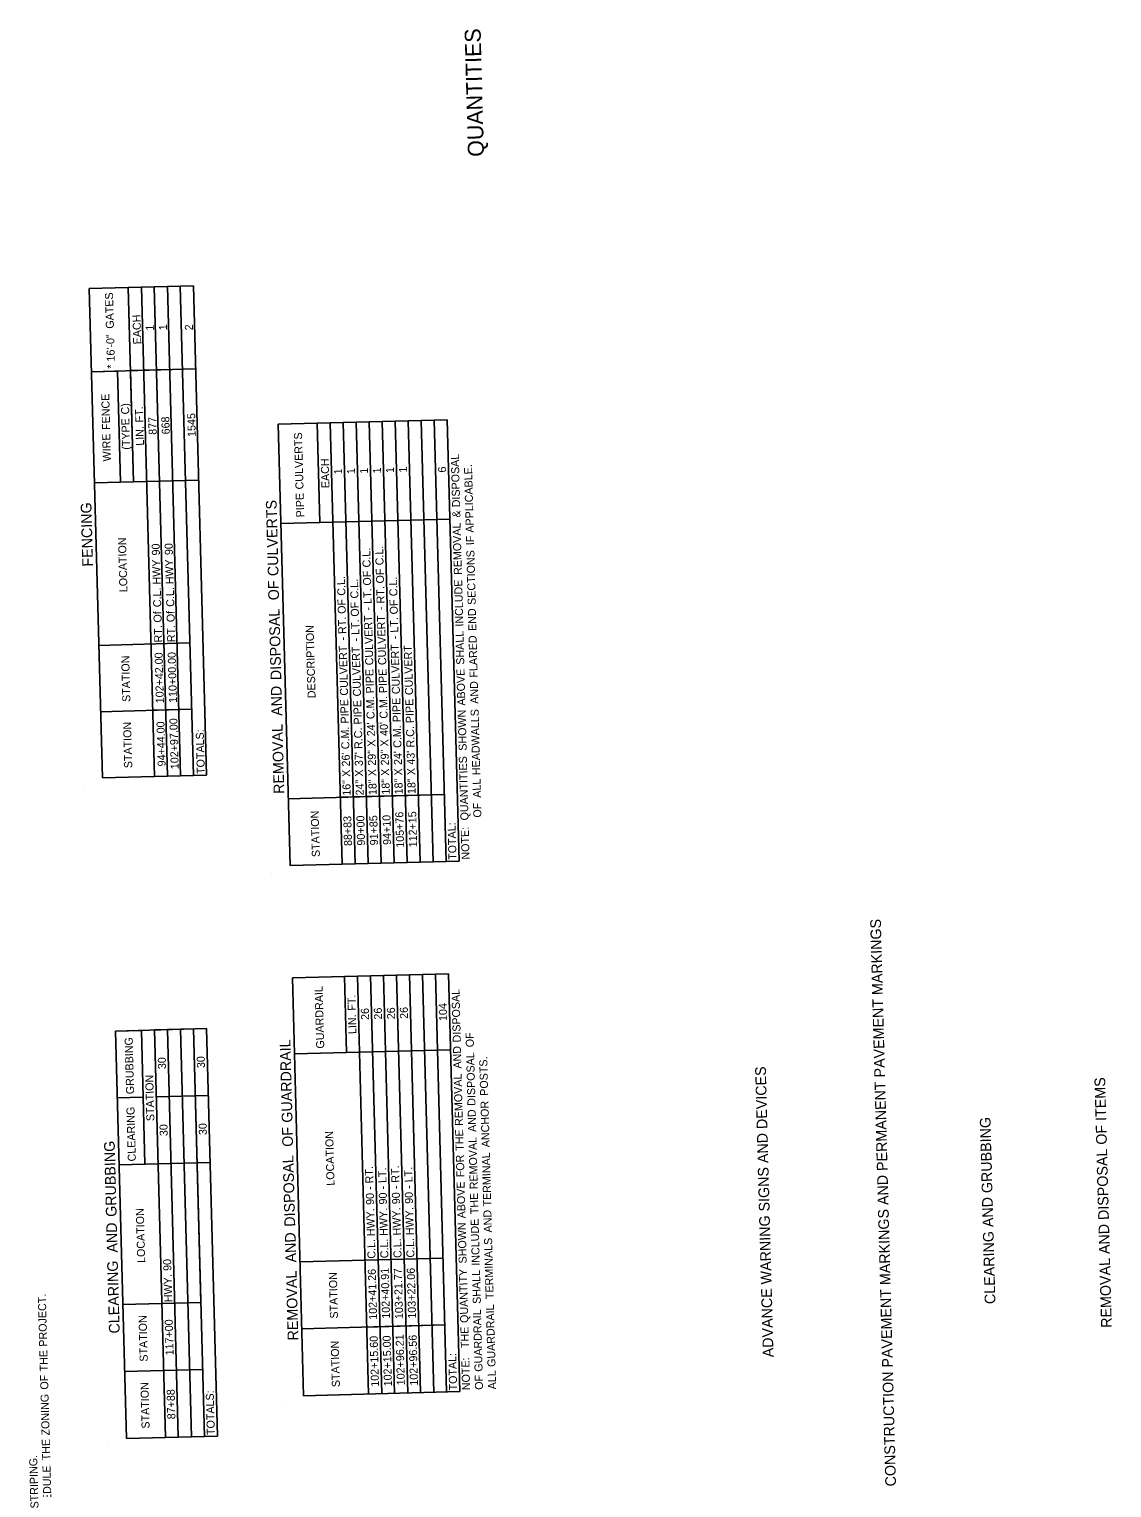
# Model space of a CAD drawing. Extents: x 1930091 to 1931962, y 596452 to 607874.
# Drawn here: x 1930986 to 1931797, y 597489 to 598583 of the extents above; entities that cross this region are included whole.
import ezdxf

# ---------------------------------------------------------------- set-up
doc = ezdxf.new("R2010")
doc.units = 0
doc.layers.add('Default', color=7, linetype='Continuous')
doc.layers.add('R_Border', color=7, linetype='Continuous')

msp = doc.modelspace()

# ---------------------------------------------------------------- linework, layer by layer
at = {"layer": 'Default'}
for p, q in [((1931109.2, 598390.2), (1931031.2, 598388.1)), ((1931041.1, 598021.1), (1931031.2, 598388.1)), ((1931109.2, 598390.2), (1931060.4, 598388.9)), ((1931064.4, 598243.1), (1931060.4, 598388.9)), ((1931080, 598022.2), (1931070.2, 598389.1)), ((1931089.8, 598022.4), (1931079.9, 598389.4)), ((1931099.5, 598022.7), (1931089.7, 598389.6)), ((1931109.3, 598022.9), (1931099.4, 598389.9)), ((1931119, 598023.2), (1931109.2, 598390.2)), ((1931110.8, 598327.8), (1931032.9, 598325.7)), ((1931052.4, 598326.2), (1931032.9, 598325.7)), ((1931054.6, 598242.9), (1931052.4, 598326.2)), ((1931091.4, 598327.3), (1931062.1, 598326.5)), ((1931064.4, 598243.1), (1931062.1, 598326.5)), ((1931110.8, 598327.8), (1931101.1, 598327.5)), ((1931299.5, 598289.7), (1931172.7, 598286.3)), ((1931299.5, 598289.7), (1931172.7, 598286.3)), ((1931181.6, 597955.4), (1931172.7, 598286.3)), ((1931204, 598212.6), (1931202, 598287.1)), ((1931204, 598212.6), (1931202, 598287.1)), ((1931220.6, 597956.5), (1931211.7, 598287.4)), ((1931230.4, 597956.8), (1931221.5, 598287.6)), ((1931240.1, 597957), (1931231.2, 598287.9)), ((1931249.9, 597957.3), (1931241, 598288.2)), ((1931259.6, 597957.5), (1931250.7, 598288.4)), ((1931269.4, 597957.8), (1931260.5, 598288.7)), ((1931279.1, 597958.1), (1931270.2, 598289)), ((1931288.8, 597958.3), (1931280, 598289.2)), ((1931298.6, 597958.6), (1931289.7, 598289.5)), ((1931308.3, 597958.8), (1931299.5, 598289.7)), ((1931113.1, 598244.5), (1931035.1, 598242.4)), ((1931113.1, 598244.5), (1931074.1, 598243.4)), ((1931301.5, 598215.2), (1931174.8, 598211.8)), ((1931301.5, 598215.2), (1931213.7, 598212.8)), ((1931106.6, 598122.4), (1931038.4, 598120.5)), ((1931106.6, 598122.4), (1931038.4, 598120.5)), ((1931107.9, 598072.7), (1931039.7, 598070.8)), ((1931107.9, 598072.7), (1931078.7, 598071.9)), ((1931119, 598023.2), (1931041.1, 598021.1)), ((1931119, 598023.2), (1931041.1, 598021.1)), ((1931297.2, 598008.8), (1931180.3, 598005.6)), ((1931297.2, 598008.8), (1931219.3, 598006.7)), ((1931308.3, 597958.8), (1931181.6, 597955.4)), ((1931308.3, 597958.8), (1931181.6, 597955.4)), ((1931300.3, 597874.4), (1931183.4, 597871.3)), ((1931300.3, 597874.4), (1931183.4, 597871.3)), ((1931191.8, 597557.9), (1931183.4, 597871.3)), ((1931223.9, 597815.3), (1931222.4, 597872.3)), ((1931240.5, 597559.2), (1931232.1, 597872.6)), ((1931250.3, 597559.5), (1931241.9, 597872.8)), ((1931260, 597559.7), (1931251.6, 597873.1)), ((1931269.8, 597560), (1931261.4, 597873.4)), ((1931279.5, 597560.3), (1931271.1, 597873.6)), ((1931289.3, 597560.5), (1931280.8, 597873.9)), ((1931299, 597560.8), (1931290.6, 597874.1)), ((1931292.1, 597817.1), (1931290.6, 597874.1)), ((1931308.8, 597561.1), (1931300.3, 597874.4)), ((1931119, 597833.3), (1931050.8, 597831.4)), ((1931070.3, 597831.9), (1931050.8, 597831.4)), ((1931059, 597525.9), (1931050.8, 597831.4)), ((1931072.9, 597731.6), (1931070.3, 597831.9)), ((1931109.2, 597833), (1931080, 597832.2)), ((1931088.2, 597526.7), (1931080, 597832.2)), ((1931097.9, 597526.9), (1931089.7, 597832.5)), ((1931107.7, 597527.2), (1931099.5, 597832.7)), ((1931117.4, 597527.4), (1931109.2, 597833)), ((1931114.7, 597627.8), (1931109.2, 597833)), ((1931127.2, 597527.7), (1931119, 597833.3)), ((1931301.9, 597817.4), (1931184.9, 597814.2)), ((1931301.9, 597817.4), (1931233.6, 597815.6)), ((1931120.3, 597783.1), (1931081.3, 597782)), ((1931120.3, 597783.1), (1931081.3, 597782)), ((1931071.6, 597781.8), (1931052.1, 597781.2)), ((1931121.7, 597732.9), (1931053.5, 597731)), ((1931111.9, 597732.6), (1931072.9, 597731.6)), ((1931296.3, 597661.2), (1931189.1, 597658.3)), ((1931296.3, 597661.2), (1931237.8, 597659.6)), ((1931114.7, 597627.8), (1931056.3, 597626.3)), ((1931114.7, 597627.8), (1931085.5, 597627)), ((1931297.7, 597611), (1931190.4, 597608.1)), ((1931297.7, 597611), (1931239.2, 597609.4)), ((1931116.1, 597577.6), (1931057.6, 597576.1)), ((1931116.1, 597577.6), (1931086.9, 597576.8)), ((1931308.8, 597561.1), (1931191.8, 597557.9)), ((1931308.8, 597561.1), (1931191.8, 597557.9)), ((1931127.2, 597527.7), (1931059, 597525.9)), ((1931127.2, 597527.7), (1931059, 597525.9))]:
    msp.add_line(p, q, dxfattribs=at)
at = {"layer": 'R_Border'}
for p, q in [((1931027.6, 598014.9), (1931027.6, 598014.9)), ((1931168.1, 597949.2), (1931168.1, 597949.2)), ((1931178.3, 597551.7), (1931178.3, 597551.7)), ((1931045.5, 597519.7), (1931045.5, 597519.7))]:
    msp.add_line(p, q, dxfattribs=at)

# ---------------------------------------------------------------- texts
at = {"layer": 'Default'}
for s, height, p in [(' GATES', 6, (1931049.7, 598355.8)), ('EACH', 6, (1931070.1, 598346.3)), (' 16\'-0"', 6, (1931050.4, 598331.2)), ('1', 6, (1931079.6, 598356.6)), ('1', 6, (1931089.4, 598356.9)), ('2', 6, (1931108.9, 598356.8)), ('*', 6, (1931050.4, 598328.1)), (' FENCE', 6, (1931046.9, 598279.9)), (' C)', 6, (1931061.2, 598291.5)), (' FT.', 6, (1931071.8, 598285.5)), ('(TYPE', 6, (1931061.8, 598267.3)), ('877', 6, (1931081.7, 598278.5)), ('668', 6, (1931091.5, 598278.8)), ('1545', 6, (1931111, 598276.9)), ('WIRE', 6, (1931047.4, 598258.5)), ('LIN.', 6, (1931072.2, 598270.3)), (' CULVERTS', 6, (1931191.8, 598235.3)), ('EACH', 6, (1931211.2, 598238.5)), ('1', 6, (1931240.1, 598249.3)), ('1', 6, (1931249.9, 598249.5)), ('1', 6, (1931259.6, 598249.8)), ('1', 6, (1931269.4, 598250.1)), ('6', 6, (1931298.6, 598250.2)), (' DISPOSAL', 6, (1931309.2, 598221.9)), (' APPLICABLE.', 6, (1931319.4, 598202.9)), ('1', 6, (1931220.7, 598248.8)), ('1', 6, (1931230.4, 598249)), ('PIPE', 6, (1931192.3, 598216.6)), ('FENCING', 8, (1931034, 598179.7)), (' CULVERTS', 8, (1931173.1, 598169.6)), (' &', 6, (1931309.4, 598214.2)), (' REMOVAL', 6, (1931310.5, 598171.2)), ('LOCATION', 6, (1931059.8, 598160.5)), (' IF', 6, (1931319.7, 598193.5)), (' 90', 6, (1931084.2, 598185.8)), (' 90', 6, (1931093.9, 598186.1)), (' C.L.', 6, (1931242.1, 598176.8)), (' C.L.', 6, (1931251.8, 598178.4)), (' SECTIONS', 6, (1931320.9, 598148.7)), (' HWY', 6, (1931084.8, 598164)), (' HWY', 6, (1931094.5, 598164.2)), (' OF', 6, (1931252.2, 598164.8)), (' OF', 8, (1931173.5, 598151.5)), (' C.L.', 6, (1931223.2, 598155.6)), (' C.L.', 6, (1931233, 598153.5)), (' OF', 6, (1931242.5, 598163.2)), (' C.L.', 6, (1931262.2, 598155.2)), (' INCLUDE', 6, (1931311.6, 598132.5)), (' C.L.', 6, (1931085.2, 598147)), (' C.L.', 6, (1931095, 598147.3)), (' OF', 6, (1931223.5, 598142)), (' LT.', 6, (1931242.8, 598149.5)), (' RT.', 6, (1931252.6, 598149.8)), (' Of', 6, (1931085.5, 598135.5)), (' Of', 6, (1931095.3, 598135.8)), (' DISPOSAL', 8, (1931175.2, 598091.6)), (' OF', 6, (1931233.3, 598139.9)), (' -', 6, (1931243, 598144.6)), (' -', 6, (1931252.7, 598144.9)), (' OF', 6, (1931262.5, 598141.6)), (' END', 6, (1931321.4, 598129.2)), ('RT.', 6, (1931085.9, 598122.8)), ('RT.', 6, (1931095.6, 598123)), ('DESCRIPTION', 6, (1931200.8, 598081)), (' RT.', 6, (1931223.9, 598126.9)), (' LT.', 6, (1931233.7, 598126.2)), (' CULVERT', 6, (1931244.1, 598103.4)), (' CULVERT', 6, (1931253.8, 598103.6)), (' LT.', 6, (1931262.9, 598127.9)), (' -', 6, (1931224.1, 598122)), (' -', 6, (1931233.8, 598121.4)), (' -', 6, (1931263, 598123.1)), (' SHALL', 6, (1931312.3, 598103.9)), (' FLARED', 6, (1931322.3, 598094.2)), ('STATION', 6, (1931062, 598078.2)), ('102+42.00', 6, (1931087.1, 598077.2)), ('110+00.00', 6, (1931096.9, 598077.5)), (' CULVERT', 6, (1931225.2, 598080.7)), (' CULVERT', 6, (1931234.9, 598080.1)), (' CULVERT', 6, (1931264.1, 598081.8)), (' CULVERT', 6, (1931273.9, 598081.1)), (' PIPE', 6, (1931244.6, 598082.4)), (' PIPE', 6, (1931254.4, 598082.6)), (' ABOVE', 6, (1931313.1, 598073.2)), (' AND', 8, (1931175.9, 598064.8)), (' AND', 6, (1931322.9, 598074.6)), (' PIPE', 6, (1931225.7, 598059.8)), (' PIPE', 6, (1931235.5, 598059.1)), (' C.M.', 6, (1931245.1, 598063.1)), (' C.M.', 6, (1931254.9, 598063.4)), (' PIPE', 6, (1931264.7, 598060.8)), (' PIPE', 6, (1931274.5, 598060.1)), (' SHOWN', 6, (1931314.1, 598039.4)), (' HEADWALLS', 6, (1931324.3, 598021.1)), ('STATION', 6, (1931063.4, 598028.5)), ('94+44.00', 6, (1931088.4, 598029.9)), ('102+97.00', 6, (1931098.2, 598027.8)), ('TOTALS:', 6, (1931117.8, 598024.2)), ('REMOVAL', 8, (1931177.4, 598009.3)), (' C.M.', 6, (1931226.2, 598040.5)), (' R.C.', 6, (1931236, 598040.7)), (" 24'", 6, (1931245.5, 598050.2)), (" 40'", 6, (1931255.2, 598050.5)), (' C.M.', 6, (1931265.2, 598041.5)), (' R.C.', 6, (1931275, 598041.8)), (' X', 6, (1931245.7, 598042.4)), (' X', 6, (1931255.4, 598042.6)), (" 26'", 6, (1931226.6, 598027.6)), (" 37'", 6, (1931236.3, 598027.9)), (' 29"', 6, (1931246.1, 598028.2)), (' 29"', 6, (1931255.8, 598028.4)), (" 24'", 6, (1931265.6, 598028.7)), (" 43'", 6, (1931275.3, 598028.9)), ('  QUANTITIES', 6, (1931315.5, 597984.9)), (' X', 6, (1931226.8, 598019.8)), (' X', 6, (1931236.5, 598020)), (' X', 6, (1931246.3, 598020.3)), (' X', 6, (1931256, 598020.6)), (' X', 6, (1931265.8, 598020.8)), (' X', 6, (1931275.5, 598021.1)), ('16"', 6, (1931227.1, 598007.9)), ('24"', 6, (1931236.9, 598008.1)), ('18"', 6, (1931246.6, 598008.4)), ('18"', 6, (1931256.4, 598008.7)), ('18"', 6, (1931266.1, 598008.9)), ('18"', 6, (1931275.8, 598009.2)), (' ALL', 6, (1931324.8, 598004.1)), ('              OF', 6, (1931325.9, 597960.3)), ('STATION', 6, (1931204, 597961.9)), ('88+83', 6, (1931228.1, 597970.2)), ('90+00', 6, (1931237.9, 597970.5)), ('91+85', 6, (1931247.6, 597970.7)), ('94+10', 6, (1931257.4, 597971)), ('105+76', 6, (1931267.2, 597968.9)), ('112+15', 6, (1931276.9, 597969.2)), ('TOTAL:', 6, (1931306.4, 597959.8)), ('NOTE:', 6, (1931316.2, 597960)), ('CONSTRUCTION PAVEMENT MARKINGS AND PERMANENT PAVEMENT MARKINGS', 8, (1931635.8, 597490.1)), ('GUARDRAIL', 6, (1931207.3, 597818.3)), (' DISPOSAL', 6, (1931309.7, 597820.7)), (' FT.', 6, (1931231, 597844.5)), ('26', 6, (1931250.6, 597840.1)), ('26', 6, (1931260.4, 597840.3)), ('26', 6, (1931270.1, 597840.6)), ('104', 6, (1931299.4, 597839)), ('LIN.', 6, (1931231.4, 597829.2)), ('26', 6, (1931240.9, 597839.8)), (' OF', 6, (1931319.5, 597817.1)), ('GRUBBING', 6, (1931064.8, 597784.1)), (' GUARDRAIL', 8, (1931183.6, 597759.8)), (' AND', 6, (1931310.2, 597801.1)), ('30', 6, (1931088.7, 597802.9)), ('30', 6, (1931117.9, 597803.7)), (' DISPOSAL', 6, (1931320.7, 597773.2)), (' POSTS.', 6, (1931330.2, 597780.7)), ('STATION', 6, (1931080, 597763.9)), (' REMOVAL', 6, (1931311.3, 597758.1)), ('ADVANCE WARNING SIGNS AND DEVICES', 8, (1931544, 597586.9)), ('REMOVAL AND DISPOSAL OF ITEMS', 8, (1931797.5, 597609)), ('CLEARING', 6, (1931066.1, 597733.7)), (' AND', 6, (1931321.2, 597753.6)), (' ANCHOR', 6, (1931331.3, 597742.1)), ('30', 6, (1931090, 597752.7)), ('30', 6, (1931119.3, 597753.5)), ('CLEARING AND GRUBBING', 8, (1931710.3, 597626.8)), (' OF', 8, (1931184, 597741.7)), ('LOCATION', 6, (1931215, 597715.5)), (' THE', 6, (1931311.8, 597739.5)), (' REMOVAL', 6, (1931322.4, 597710.6)), (' GRUBBING', 8, (1931051.8, 597689.2)), (' TERMINAL', 6, (1931332.5, 597697.7)), (' DISPOSAL', 8, (1931185.6, 597681.8)), (' RT.', 6, (1931244.2, 597715)), (' LT.', 6, (1931254, 597715.3)), (' RT.', 6, (1931263.7, 597715.5)), (' LT.', 6, (1931273.5, 597715.8)), (' FOR', 6, (1931312.4, 597719.6)), (' ABOVE', 6, (1931313.2, 597688.8)), (' 90', 6, (1931244.7, 597698.9)), (' -', 6, (1931244.4, 597710.1)), (' 90', 6, (1931254.4, 597699.2)), (' -', 6, (1931254.1, 597710.4)), (' 90', 6, (1931264.2, 597699.4)), (' -', 6, (1931263.8, 597710.7)), (' 90', 6, (1931273.9, 597699.7)), (' -', 6, (1931273.6, 597710.9)), (' THE', 6, (1931322.9, 597691.9)), ('LOCATION', 6, (1931073.1, 597657.6)), (' HWY.', 6, (1931245.3, 597675.4)), (' HWY.', 6, (1931255, 597675.7)), (' HWY.', 6, (1931264.8, 597676)), (' HWY.', 6, (1931274.5, 597676.2)), (' AND', 6, (1931333, 597678.2)), (' AND', 8, (1931052.5, 597662.4)), (' SHOWN', 6, (1931314.1, 597655)), (' INCLUDE', 6, (1931323.9, 597653.3)), (' AND', 8, (1931186.4, 597655)), ('C.L.', 6, (1931245.7, 597660.8)), ('C.L.', 6, (1931255.4, 597661.1)), ('C.L.', 6, (1931265.2, 597661.3)), ('C.L.', 6, (1931274.9, 597661.6)), (' TERMINALS', 6, (1931334.3, 597628.3)), ('CLEARING', 8, (1931054, 597604.7)), (' 90', 6, (1931092.8, 597649.4)), ('102+41.26', 6, (1931246.9, 597615)), ('102+40.91', 6, (1931256.6, 597615.8)), ('103+21.77', 6, (1931266.4, 597615.5)), ('103+22.06', 6, (1931276.1, 597615.8)), (' QUANTITY', 6, (1931315.3, 597610.4)), (' SHALL', 6, (1931324.7, 597624.7)), ('HWY.', 6, (1931093.4, 597628.2)), ('REMOVAL', 8, (1931187.9, 597599.5)), ('STATION', 6, (1931217.6, 597615.9)), (' PROJECT.', 6, (1930999.7, 597592.6)), (' GUARDRAIL', 6, (1931326, 597573.8)), (' GUARDRAIL', 6, (1931335.7, 597577.4)), ('STATION', 6, (1931075, 597583.6)), ('117+00', 6, (1931094.4, 597588.3)), ('   THE', 6, (1931315.9, 597587.1)), ('STATION', 6, (1931219, 597564.5)), ('102+15.60', 6, (1931248.3, 597564.8)), ('102+15.00', 6, (1931258, 597565.1)), ('102+96.21', 6, (1931267.7, 597565.9)), ('102+96.56', 6, (1931277.5, 597565.6)), (' THE', 6, (1931000.2, 597574)), ('TOTAL:', 6, (1931306.9, 597562)), ('NOTE:', 6, (1931316.6, 597562.2)), ('ALL', 6, (1931336.1, 597562.8)), (' OF', 6, (1931000.6, 597560.4)), ('STATION', 6, (1931076.4, 597533.4)), ('OF', 6, (1931326.3, 597562.5)), (' ZONING', 6, (1931001.5, 597526)), ('87+88', 6, (1931095.7, 597540.4)), ('TOTALS:', 6, (1931125.3, 597528.6)), (' THE', 6, (1931002, 597507.4)), (' STRIPING.', 6, (1930993.2, 597471.3)), (' SCHEDULE', 6, (1931003.3, 597459.9))]:
    msp.add_text(s, height=height, rotation=91.5377, dxfattribs=at).set_placement(p)
at = {"layer": 'R_Border'}
msp.add_text('QUANTITIES', height=12, rotation=91.5377, dxfattribs=at).set_placement((1931327, 598487))

doc.saveas('drawing.dxf')
